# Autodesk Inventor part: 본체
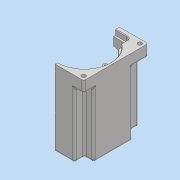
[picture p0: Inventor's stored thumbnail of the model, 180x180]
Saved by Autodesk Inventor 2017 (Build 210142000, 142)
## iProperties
Part Number: 본체
Material: 일반
Document SubType Name: Modeling
Designer: user
Density: 1 g/cm^3
Appearance: 기본값
Author: user
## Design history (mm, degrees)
sketch "스케치1"
  geometry: L1 (-49, 60)-(49, 60); L2 (49, 60)-(49, -50); L3 (49, -50)-(-49, -50); L4 (-49, -50)-(-49, 60); 2 further points
  constraints: 8 end point, 2 parallel, 1 horizontal, 1 midpoint, 1 perpendicular, 1 vertical alignment
  dimensions: "d0" = 98 distance of L2.end L3.end; "d1" = 110 distance of L1.end L2.end; "d2" = 50 distance from line of point (0, 0) L3
extrude "돌출1" new body sketch "스케치1" distance "d3" = 130; taper "d4" = 0 deg
sketch "스케치9"
  geometry: L1 (-49, 60)-(-33, 60); L2 (-33, 60)-(-33, 33); L3 (-33, 33)-(-49, 33); L4 (-49, 33)-(-49, 60); L5 (49, 60)-(33, 60); L6 (33, 60)-(33, 33); L7 (33, 33)-(49, 33); L8 (49, 33)-(49, 60); L9 (-49, -50)-(-33, -50); L10 (-33, -50)-(-33, -33); L11 (-33, -33)-(-49, -33); L12 (-49, -33)-(-49, -50); L13 (49, -50)-(33, -50); L14 (33, -50)-(33, -33); L15 (33, -33)-(49, -33); L16 (49, -33)-(49, -50); 1 further point
  constraints: 32 end point, 8 parallel, 4 horizontal, 4 perpendicular
  dimensions: "d84" = 16 distance of L2.end L3.end; "d85" = 27 distance of L1.end L2.end; "d86" = 16 distance of L7.end L6.end; "d87" = 27 distance of L6.end L5.end; "d88" = 16 distance of L11.end L10.end; "d89" = 17 distance of L10.end L9.end; "d90" = 16 distance of L14.end L15.end; "d91" = 17 distance of L13.end L14.end
extrude "돌출9" cut sketch "스케치9" distance "d92" = 110; taper "d93" = 0 deg
fillet "모깎기12" dims "d94" = 3
sketch "스케치2"
  geometry: L1 (-23, 50)-(23, 50); L2 (23, 50)-(23, 35.143); L3 (-23, 35.143)-(-23, 50); A1 r 42 centre (0, 0) between (-23, 35.143) and (23, 35.143); 2 further points
  constraints: 6 end point, 2 point on circle, 1 centre point, 1 coincident, 1 horizontal, 1 midpoint, 1 parallel, 1 perpendicular, 1 vertical alignment
  dimensions: "d5" = 84 diameter of A1; "d6" = 50 distance from line of point (0, 0) L1; "d7" = 46 distance of L1.start L1.end
extrude "돌출2" cut sketch "스케치2" distance "d8" = 121; taper "d9" = 0 deg
sketch "스케치3"
  geometry: L1 (-23, 35.143)-(-23, 50) reference; L2 (-23, 50)-(23, 50) reference; L3 (23, 50)-(23, 35.143) reference; L4 (-26, 36.729)-(-26, 53); L5 (-26, 53)-(26, 53); L6 (26, 53)-(26, 36.729); A1 r 42 centre (0, 0) between (-23, 35.143) and (23, 35.143) reference; A2 r 45 centre (0, 0) between (-26, 36.729) and (26, 36.729)
  constraints: 6 end point, 2 point on circle, 1 centre point, 3 other
  dimensions: "d10" = 3 radial gap between concentric circles of A2 A1
extrude "돌출3" cut sketch "스케치3" distance "d11" = 9; taper "d12" = 0 deg
fillet "모깎기1" dims "d13" = 6
fillet "모깎기2" dims "d14" = 3
fillet "모깎기3" dims "d15" = 3
fillet "모깎기4" dims "d16" = 6
sketch "스케치4"
  geometry: L1 (36, 4)-(41.809, 4); L2 (36, -4)-(41.809, -4); A1 r 45 centre (0, 0) between (-27.188, 35.859) and (27.188, 35.859) reference; A2 r 42 centre (0, 0) between (-25.375, 33.468) and (25.375, 33.468) reference; A3 r 4 centre (36, 0) between (36, 4) and (36, -4)
  constraints: 4 end point, 4 point on circle, 2 horizontal, 2 tangent, 1 centre point, 1 horizontal alignment
  dimensions: "d17" = 8 diameter of A3; "d18" = 36 distance of A3.centre A1.centre
extrude "돌출4" join sketch "스케치4" stored distance "d19" = 9; taper "d20" = 0 deg
hole "구멍1" diameter "d23" = 3.242; stored, may be unused: countersink angle "d27" = 90 deg, drill point angle "d29" = 118 deg; dims "d21" = 10, "d22" = 10, "d24" = 7, "d25" = 4, "d26" = 2, "d28" = 9
sketch "스케치5"
  geometry: A1 r 42 centre (0, 0) between (-41.809, -4) and (41.809, -4) reference; A2 r 42 centre (0, 0) between (41.809, 4) and (25.375, 33.468) reference; A3 r 21 centre (0, 11) between (8.978, -7.984) and (-8.978, -7.984); A4 r 15 centre (0, -20) between (-8.978, -7.984) and (8.978, -7.984)
  constraints: 4 point on circle, 2 centre point, 2 vertical alignment
  dimensions: "d30" = 42 diameter of A3; "d31" = 30 diameter of A4; "d32" = 11 distance of A1.centre A3.centre; "d33" = 20 distance of A4.centre A1.centre
extrude "돌출5" join sketch "스케치5" distance "d34" = 7; taper "d35" = 0 deg
fillet "모깎기5" dims "d36" = 3
hole "구멍2" diameter "d39" = 19; stored, may be unused: countersink angle "d43" = 90 deg, drill point angle "d45" = 0 deg; dims "d37" = 10, "d38" = 10, "d40" = 7, "d41" = 22, "d42" = 7, "d44" = 10
fillet "모깎기6" dims "d46" = 0.3
chamfer "모따기1" distance "d47" = 1; stored, may be unused: second distance "d48" = 2, angle "d49" = 45 deg
fillet "모깎기7" dims "d50" = 3
hole "구멍3" diameter "d53" = 28; stored, may be unused: countersink angle "d57" = 90 deg, drill point angle "d59" = 0 deg; dims "d51" = 10, "d52" = 10, "d54" = 7, "d55" = 35, "d56" = 10, "d58" = 10
sketch "스케치6"
  geometry: L1 (27, -16)-(-27, -16); L2 (-27, -16)-(-27, 38); L3 (-27, 38)-(27, 38); L4 (27, 38)-(27, -16); L5 (27, -16)-(-27, 38); L6 (-27, -16)-(27, 38); C1 r 14 at (0, 11) reference; 1 further point
  constraints: 12 end point, 2 midpoint, 2 parallel, 1 horizontal, 1 perpendicular
  dimensions: "d60" = 54 distance of L2.end L3.end; "d61" = 54 distance of L1.end L2.end
extrude "돌출6" join sketch "스케치6" distance "d62" = 7; taper "d63" = 0 deg
sketch "스케치7"
  geometry: C1 r 14 at (0, 11) reference; C2 r 16 at (0, 11); 1 further point
  constraints: 1 centre point, 1 coincident
  dimensions: "d64" = 32 diameter of C2
extrude "돌출7" cut sketch "스케치7" distance "d65" = 8.3; taper "d66" = 0 deg
chamfer "모따기2" distance "d67" = 0.8; stored, may be unused: second distance "d68" = 2, angle "d69" = 30 deg
fillet "모깎기8" dims "d70" = 0.3
fillet "모깎기9" dims "d71" = 0.3
fillet "모깎기10" dims "d72" = 3
fillet "모깎기11" dims "d73" = 3
fillet "모깎기13" dims "d95" = 3
fillet "모깎기14" dims "d96" = 3
fillet "모깎기15" dims "d97" = 3
sketch "스케치10"
  geometry: L1 (-46, 60)-(46, 60) reference; A1 r 45 centre (0, 0) between (-27.188, 35.859) and (27.188, 35.859) reference; 4 further points
  constraints: 2 horizontal alignment, 2 vertical alignment
  dimensions: "d98" = 84 distance of point (42, 53) point (-42, 53); "d99" = 42 horizontal distance of A1.centre point (42, 53) (= 0.5 x d98); "d100" = 96 distance of point (42, -43) point (42, 53); "d101" = 7 distance from line of L1 point (42, 53)
hole "구멍4" sketch "스케치10" at (-42, 53), (-42, -43), (42, -43), (42, 53) diameter "d102" = 7; stored, may be unused: countersink angle "d106" = 90 deg, drill point angle "d108" = 0 deg; dims "d103" = 7, "d104" = 35, "d105" = 10, "d107" = 10
sketch "스케치11"
  geometry: L1 (0, 0)-(92, 0) reference; C1 r 15 at (46, 89); C2 r 22.5 at (46, 40); 2 further points
  constraints: 2 centre point, 2 vertical alignment, 1 midpoint
  dimensions: "d109" = 30 diameter of C1; "d110" = 45 diameter of C2; "d111" = 40 distance from line of C2.centre L1; "d112" = 49 distance of C1.centre C2.centre
extrude "돌출10" join sketch "스케치11" distance "d113" = 5; taper "d114" = 0 deg
extrude "돌출11" join sketch "스케치11" distance "d115" = 10; taper "d116" = 0 deg
hole "구멍5" diameter "d119" = 20; stored, may be unused: countersink angle "d123" = 90 deg, drill point angle "d125" = 0 deg; dims "d117" = 10, "d118" = 10, "d120" = 7, "d121" = 30, "d122" = 5, "d124" = 10
hole "구멍6" diameter "d128" = 33.376; stored, may be unused: countersink angle "d132" = 90 deg, drill point angle "d134" = 0 deg; dims "d126" = 10, "d127" = 10, "d129" = 70, "d130" = 30, "d131" = 5, "d133" = 77.3
fillet "모깎기16" dims "d135" = 3
sketch "스케치12"
  geometry: L1 (-23, 80)-(-127, 80) reference; L2 (-130, 104)-(-130, 83) reference; 2 further points
  constraints: 1 other
  dimensions: "d136" = 33 distance from line of point (-65, 47) L1; "d137" = 65 distance from line of point (-65, 47) L2
feature "엠보싱1" sketch "스케치12" dims "d138" = 0.5, "d139" = 0
fillet "모깎기17" dims "d140" = 3
fillet "모깎기18" dims "d141" = 3
chamfer "모따기3" distance "d142" = 1; stored, may be unused: second distance "d143" = 2, angle "d144" = 30 deg
chamfer "모따기4" distance "d145" = 1; stored, may be unused: second distance "d146" = 2, angle "d147" = 45 deg
chamfer "모따기5" distance "d148" = 1; stored, may be unused: second distance "d149" = 2, angle "d150" = 45 deg
node "솔리드1"
mirror "미러1"
